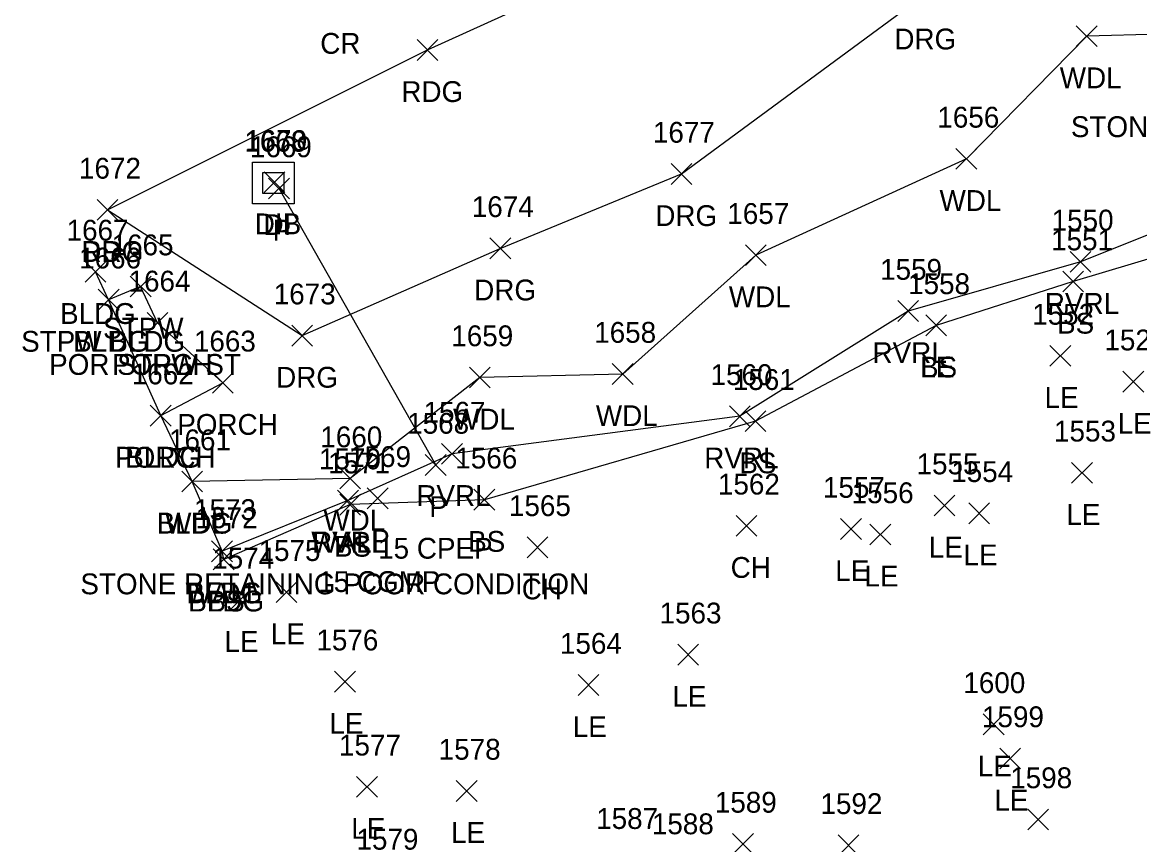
# Model space of a CAD drawing. Extents: x 1620157 to 1620595, y 115111 to 117885.
# Drawn here: x 1620193.5 to 1620300.9, y 115358.6 to 115437.5 of the extents above; entities that cross this region are included whole.
import ezdxf

# ---------------------------------------------------------------- set-up
doc = ezdxf.new("R2010")
doc.units = 0
for name, color, linetype in [('D_A', 7, 'Continuous'), ('D_C', 7, 'Continuous'), ('D_I', 7, 'Continuous'), ('D_TIC', 7, 'Continuous'), ('DCP', 7, 'Continuous'), ('DS', 7, 'Continuous'), ('L_A', 7, 'Continuous'), ('L_C', 7, 'Continuous'), ('L_I', 7, 'Continuous'), ('L_TIC', 7, 'Continuous'), ('LAWA', 7, 'Continuous'), ('LAWE', 7, 'Continuous'), ('LBC', 7, 'Continuous'), ('LBF', 7, 'Continuous'), ('LELB', 7, 'Continuous'), ('LW', 7, 'Continuous'), ('P_A', 7, 'Continuous'), ('P_I', 7, 'Continuous'), ('P_TIC', 7, 'Continuous'), ('PEU', 7, 'Continuous'), ('R_A', 7, 'Continuous'), ('R_I', 7, 'Continuous'), ('R_TIC', 7, 'Continuous'), ('RDG', 7, 'Continuous')]:
    doc.layers.add(name, color=color, linetype=linetype)

msp = doc.modelspace()

# ---------------------------------------------------------------- linework, layer by layer
at = {"layer": 'D_TIC'}
for points in [[(1620216.75, 115421.19), (1620218.75, 115423.19)], [(1620218.75, 115421.19), (1620216.75, 115423.19)], [(1620217.18, 115420.59), (1620219.18, 115422.59)], [(1620219.18, 115420.59), (1620217.18, 115422.59)], [(1620232.23, 115394.04), (1620234.23, 115396.04)], [(1620234.23, 115394.04), (1620232.23, 115396.04)], [(1620226.65, 115390.84), (1620228.65, 115392.84)], [(1620228.65, 115390.84), (1620226.65, 115392.84)]]:
    msp.add_lwpolyline(points, dxfattribs=at)
at = {"layer": 'DCP'}
msp.add_lwpolyline([(1620233.23, 115395.04), (1620218.18, 115421.59)], dxfattribs=at)
at = {"layer": 'DS'}
for p, q in [((1620215.63, 115424.12), (1620219.63, 115424.12)), ((1620215.63, 115420.12), (1620215.63, 115424.12)), ((1620219.63, 115424.12), (1620219.63, 115420.12)), ((1620216.63, 115421.12), (1620216.63, 115423.12)), ((1620216.63, 115423.12), (1620218.63, 115423.12)), ((1620218.63, 115423.12), (1620218.63, 115421.12)), ((1620218.63, 115421.12), (1620216.63, 115421.12)), ((1620217.64, 115422.12), (1620217.64, 115422.12)), ((1620217.64, 115422.12), (1620217.64, 115422.12)), ((1620219.63, 115420.12), (1620215.63, 115420.12))]:
    msp.add_line(p, q, dxfattribs=at)
at = {"layer": 'L_TIC'}
for points in [[(1620294.78, 115435.21), (1620296.78, 115437.21)], [(1620296.78, 115435.21), (1620294.78, 115437.21)], [(1620283.22, 115423.43), (1620285.22, 115425.43)], [(1620285.22, 115423.43), (1620283.22, 115425.43)], [(1620262.99, 115414.18), (1620264.99, 115416.18)], [(1620264.99, 115414.18), (1620262.99, 115416.18)], [(1620294.19, 115413.55), (1620296.19, 115415.55)], [(1620296.19, 115413.55), (1620294.19, 115415.55)], [(1620199.55, 115412.58), (1620201.55, 115414.58)], [(1620201.55, 115412.58), (1620199.55, 115414.58)], [(1620293.48, 115411.65), (1620295.48, 115413.65)], [(1620295.48, 115411.65), (1620293.48, 115413.65)], [(1620203.88, 115411.17), (1620205.88, 115413.17)], [(1620205.88, 115411.17), (1620203.88, 115413.17)], [(1620200.81, 115409.91), (1620202.81, 115411.91)], [(1620202.81, 115409.91), (1620200.81, 115411.91)], [(1620200.81, 115409.91), (1620202.81, 115411.91)], [(1620202.81, 115409.91), (1620200.81, 115411.91)], [(1620277.63, 115408.82), (1620279.63, 115410.82)], [(1620279.63, 115408.82), (1620277.63, 115410.82)], [(1620205.5, 115407.69), (1620207.5, 115409.69)], [(1620207.5, 115407.69), (1620205.5, 115409.69)], [(1620205.5, 115407.69), (1620207.5, 115409.69)], [(1620207.5, 115407.69), (1620205.5, 115409.69)], [(1620280.32, 115407.44), (1620282.32, 115409.44)], [(1620282.32, 115407.44), (1620280.32, 115409.44)], [(1620280.32, 115407.44), (1620282.32, 115409.44)], [(1620282.32, 115407.44), (1620280.32, 115409.44)], [(1620292.24, 115404.51), (1620294.24, 115406.51)], [(1620294.24, 115404.51), (1620292.24, 115406.51)], [(1620236.48, 115402.44), (1620238.48, 115404.44)], [(1620238.48, 115402.44), (1620236.48, 115404.44)], [(1620250.2, 115402.77), (1620252.2, 115404.77)], [(1620252.2, 115402.77), (1620250.2, 115404.77)], [(1620299.26, 115402.04), (1620301.26, 115404.04)], [(1620301.26, 115402.04), (1620299.26, 115404.04)], [(1620211.78, 115401.93), (1620213.78, 115403.93)], [(1620213.78, 115401.93), (1620211.78, 115403.93)], [(1620205.81, 115398.78), (1620207.81, 115400.78)], [(1620207.81, 115398.78), (1620205.81, 115400.78)], [(1620205.81, 115398.78), (1620207.81, 115400.78)], [(1620207.81, 115398.78), (1620205.81, 115400.78)], [(1620261.46, 115398.71), (1620263.46, 115400.71)], [(1620263.46, 115398.71), (1620261.46, 115400.71)], [(1620262.96, 115398.24), (1620264.96, 115400.24)], [(1620264.96, 115398.24), (1620262.96, 115400.24)], [(1620233.8, 115395.1), (1620235.8, 115397.1)], [(1620235.8, 115395.1), (1620233.8, 115397.1)], [(1620208.83, 115392.45), (1620210.83, 115394.45)], [(1620210.83, 115392.45), (1620208.83, 115394.45)], [(1620208.83, 115392.45), (1620210.83, 115394.45)], [(1620210.83, 115392.45), (1620208.83, 115394.45)], [(1620224.02, 115392.74), (1620226.02, 115394.74)], [(1620226.02, 115392.74), (1620224.02, 115394.74)], [(1620294.33, 115393.29), (1620296.33, 115395.29)], [(1620296.33, 115393.29), (1620294.33, 115395.29)], [(1620223.8, 115390.62), (1620225.8, 115392.62)], [(1620225.8, 115390.62), (1620223.8, 115392.62)], [(1620223.8, 115390.62), (1620225.8, 115392.62)], [(1620225.8, 115390.62), (1620223.8, 115392.62)], [(1620224.01, 115390.23), (1620226.01, 115392.23)], [(1620226.01, 115390.23), (1620224.01, 115392.23)], [(1620236.91, 115390.7), (1620238.91, 115392.7)], [(1620238.91, 115390.7), (1620236.91, 115392.7)], [(1620281.12, 115390.14), (1620283.12, 115392.14)], [(1620283.12, 115390.14), (1620281.12, 115392.14)], [(1620284.45, 115389.4), (1620286.45, 115391.4)], [(1620286.45, 115389.4), (1620284.45, 115391.4)], [(1620262.09, 115388.2), (1620264.09, 115390.2)], [(1620264.09, 115388.2), (1620262.09, 115390.2)], [(1620272.13, 115387.89), (1620274.13, 115389.89)], [(1620274.13, 115387.89), (1620272.13, 115389.89)], [(1620274.95, 115387.37), (1620276.95, 115389.37)], [(1620276.95, 115387.37), (1620274.95, 115389.37)], [(1620242.01, 115386.13), (1620244.01, 115388.13)], [(1620244.01, 115386.13), (1620242.01, 115388.13)], [(1620211.7, 115385.75), (1620213.7, 115387.75)], [(1620213.7, 115385.75), (1620211.7, 115387.75)], [(1620211.7, 115385.75), (1620213.7, 115387.75)], [(1620213.7, 115385.75), (1620211.7, 115387.75)], [(1620211.86, 115384.97), (1620213.86, 115386.97)], [(1620213.86, 115384.97), (1620211.86, 115386.97)], [(1620211.86, 115384.97), (1620213.86, 115386.97)], [(1620213.86, 115384.97), (1620211.86, 115386.97)], [(1620217.9, 115381.82), (1620219.9, 115383.82)], [(1620219.9, 115381.82), (1620217.9, 115383.82)], [(1620213.45, 115381.09), (1620215.45, 115383.09)], [(1620215.45, 115381.09), (1620213.45, 115383.09)], [(1620256.48, 115375.82), (1620258.48, 115377.82)], [(1620258.48, 115375.82), (1620256.48, 115377.82)], [(1620223.52, 115373.23), (1620225.52, 115375.23)], [(1620225.52, 115373.23), (1620223.52, 115375.23)], [(1620246.91, 115372.91), (1620248.91, 115374.91)], [(1620248.91, 115372.91), (1620246.91, 115374.91)], [(1620285.84, 115369.13), (1620287.84, 115371.13)], [(1620287.84, 115369.13), (1620285.84, 115371.13)], [(1620287.42, 115365.86), (1620289.42, 115367.86)], [(1620289.42, 115365.86), (1620287.42, 115367.86)], [(1620225.63, 115363.14), (1620227.63, 115365.14)], [(1620227.63, 115363.14), (1620225.63, 115365.14)], [(1620235.21, 115362.74), (1620237.21, 115364.74)], [(1620237.21, 115362.74), (1620235.21, 115364.74)], [(1620290.12, 115360), (1620292.12, 115362)], [(1620292.12, 115360), (1620290.12, 115362)], [(1620261.75, 115357.65), (1620263.75, 115359.65)], [(1620263.75, 115357.65), (1620261.75, 115359.65)], [(1620271.9, 115357.52), (1620273.9, 115359.52)], [(1620273.9, 115357.52), (1620271.9, 115359.52)]]:
    msp.add_lwpolyline(points, dxfattribs=at)
at = {"layer": 'LAWA'}
msp.add_lwpolyline([(1620309.96, 115436.61), (1620295.78, 115436.21), (1620284.22, 115424.43), (1620263.99, 115415.18), (1620251.2, 115403.77), (1620237.48, 115403.44), (1620225.02, 115393.74), (1620209.83, 115393.45)], dxfattribs=at)
at = {"layer": 'LAWE'}
msp.add_lwpolyline([(1620317.3, 115432.59), (1620311.75, 115429.38), (1620305.53, 115418.67), (1620295.19, 115414.55), (1620278.63, 115409.82), (1620262.46, 115399.71), (1620234.8, 115396.1), (1620224.8, 115391.62)], dxfattribs=at)
at = {"layer": 'LBC'}
msp.add_lwpolyline([(1620212.86, 115385.97), (1620212.7, 115386.75), (1620209.83, 115393.45), (1620206.81, 115399.78), (1620201.81, 115410.91), (1620200.55, 115413.58)], dxfattribs=at)
at = {"layer": 'LBF'}
for points in [[(1620206.5, 115408.69), (1620204.88, 115412.17), (1620201.81, 115410.91)], [(1620206.81, 115399.78), (1620212.78, 115402.93), (1620206.5, 115408.69)]]:
    msp.add_lwpolyline(points, dxfattribs=at)
at = {"layer": 'LELB'}
msp.add_lwpolyline([(1620445.93, 115434.7), (1620432.19, 115440.31), (1620415.15, 115443.99), (1620397.76, 115444.06), (1620388.34, 115442.49), (1620368.19, 115442.37), (1620354.52, 115441.05), (1620350.88, 115433.96), (1620346.48, 115432.5), (1620338.97, 115434.36), (1620325.33, 115430.43), (1620316.03, 115427.32), (1620308.72, 115416.91), (1620294.48, 115412.65), (1620281.32, 115408.44), (1620263.96, 115399.24), (1620237.91, 115391.7), (1620225.01, 115391.23), (1620212.86, 115385.97)], dxfattribs=at)
at = {"layer": 'LW'}
msp.add_lwpolyline([(1620224.8, 115391.62), (1620212.7, 115386.75)], dxfattribs=at)
at = {"layer": 'P_TIC'}
for points in [[(1620231.44, 115433.89), (1620233.44, 115435.89)], [(1620233.44, 115433.89), (1620231.44, 115435.89)], [(1620200.7, 115418.53), (1620202.7, 115420.53)], [(1620202.7, 115418.53), (1620200.7, 115420.53)]]:
    msp.add_lwpolyline(points, dxfattribs=at)
at = {"layer": 'PEU'}
msp.add_lwpolyline([(1620201.7, 115419.53), (1620232.44, 115434.89), (1620251.19, 115443.43), (1620278.49, 115455.42), (1620293.82, 115465.58)], dxfattribs=at)
at = {"layer": 'R_TIC'}
for points in [[(1620255.84, 115421.98), (1620257.84, 115423.98)], [(1620257.84, 115421.98), (1620255.84, 115423.98)], [(1620200.7, 115418.53), (1620202.7, 115420.53)], [(1620202.7, 115418.53), (1620200.7, 115420.53)], [(1620238.44, 115414.84), (1620240.44, 115416.84)], [(1620240.44, 115414.84), (1620238.44, 115416.84)], [(1620219.41, 115406.46), (1620221.41, 115408.46)], [(1620221.41, 115406.46), (1620219.41, 115408.46)]]:
    msp.add_lwpolyline(points, dxfattribs=at)
at = {"layer": 'RDG'}
msp.add_lwpolyline([(1620201.7, 115419.53), (1620220.41, 115407.46), (1620239.44, 115415.84), (1620256.84, 115422.98), (1620279.82, 115439.94), (1620293.82, 115465.58)], dxfattribs=at)

# ---------------------------------------------------------------- texts
at = {"layer": 'D_A'}
for s, p in [('DIB', (1620215.85, 115417.19)), ('DI', (1620216.69, 115417.12)), ('P', (1620217.56, 115416.59)), ('P', (1620232.61, 115390.04)), ('P', (1620227.03, 115386.84))]:
    msp.add_text(s, height=2, dxfattribs=at).set_placement(p)
at = {"layer": 'D_C'}
for s, p in [('15 CPEP', (1620227.7, 115386.04)), ('15 CGMP', (1620221.94, 115382.84))]:
    msp.add_text(s, height=2, dxfattribs=at).set_placement(p)
at = {"layer": 'D_I'}
for s, p in [('1668', (1620214.85, 115425.12)), ('1670', (1620214.92, 115425.19)), ('1669', (1620215.38, 115424.59)), ('1568', (1620230.49, 115398.04)), ('1569', (1620224.91, 115394.84))]:
    msp.add_text(s, height=2, dxfattribs=at).set_placement(p)
at = {"layer": 'L_A'}
for s, p in [('WDL', (1620293.19, 115431.21)), ('WDL', (1620281.64, 115419.43)), ('WDL', (1620261.4, 115410.18)), ('RVRL', (1620291.76, 115409.55)), ('BLDG', (1620197.14, 115408.58)), ('BS', (1620292.93, 115407.65)), ('STPW', (1620201.27, 115407.17)), ('STPW BLDG', (1620193.4, 115405.91)), ('BLDG', (1620198.4, 115405.91)), ('RVRL', (1620275.2, 115404.82)), ('POR STPW ST', (1620196.09, 115403.69)), ('PORCH', (1620202.13, 115403.69)), ('BS', (1620279.76, 115403.44)), ('LE', (1620279.8, 115403.44)), ('LE', (1620291.73, 115400.51)), ('WDL', (1620248.62, 115398.77)), ('PORCH', (1620208.4, 115397.93)), ('WDL', (1620234.9, 115398.44)), ('LE', (1620298.75, 115398.04)), ('PORCH', (1620202.43, 115394.78)), ('BLDG', (1620203.4, 115394.78)), ('RVRL', (1620259.03, 115394.71)), ('BS', (1620262.4, 115394.24)), ('RVRL', (1620231.37, 115391.1)), ('LE', (1620293.82, 115389.29)), ('BLDG', (1620206.42, 115388.45)), ('WDL', (1620207.24, 115388.45)), ('WDL', (1620222.44, 115388.74)), ('WALL', (1620221.28, 115386.62)), ('RVRL', (1620221.36, 115386.62)), ('BS', (1620223.46, 115386.23)), ('BS', (1620236.35, 115386.7)), ('LE', (1620280.61, 115386.14)), ('LE', (1620283.94, 115385.4)), ('CH', (1620261.57, 115384.2)), ('LE', (1620271.62, 115383.89)), ('LE', (1620274.43, 115383.37)), ('WALL', (1620209.19, 115381.75)), ('BLDG', (1620209.29, 115381.75)), ('CH', (1620241.5, 115382.13)), ('BLDG', (1620209.45, 115380.97)), ('BS', (1620211.3, 115380.97)), ('LE', (1620217.39, 115377.82)), ('LE', (1620212.94, 115377.09)), ('LE', (1620255.97, 115371.82)), ('LE', (1620223.01, 115369.23)), ('LE', (1620246.4, 115368.91)), ('LE', (1620285.32, 115365.13)), ('LE', (1620286.91, 115361.86)), ('LE', (1620225.12, 115359.14)), ('LE', (1620234.7, 115358.74))]:
    msp.add_text(s, height=2, dxfattribs=at).set_placement(p)
at = {"layer": 'L_C'}
for s, p in [('STONE RETAINING', (1620294.26, 115426.52)), ('STONE RETAINING POOR CONDITION', (1620199.09, 115382.62))]:
    msp.add_text(s, height=2, dxfattribs=at).set_placement(p)
at = {"layer": 'L_I'}
for s, p in [('1656', (1620281.43, 115427.43)), ('1657', (1620261.25, 115418.18)), ('1550', (1620292.41, 115417.55)), ('1667', (1620197.77, 115416.58)), ('1665', (1620202.09, 115415.17)), ('1551', (1620292.36, 115415.65)), ('1666', (1620198.97, 115413.91)), ('1666', (1620198.97, 115413.91)), ('1559', (1620275.93, 115412.82)), ('1664', (1620203.72, 115411.69)), ('1664', (1620203.72, 115411.69)), ('1558', (1620278.62, 115411.44)), ('1558', (1620278.62, 115411.44)), ('1552', (1620290.55, 115408.51)), ('1659', (1620234.73, 115406.44)), ('1658', (1620248.46, 115406.77)), ('1663', (1620210, 115405.93)), ('1520', (1620297.48, 115406.04)), ('1662', (1620204.03, 115402.78)), ('1662', (1620204.03, 115402.78)), ('1560', (1620259.64, 115402.71)), ('1561', (1620261.78, 115402.24)), ('1567', (1620232.06, 115399.1)), ('1660', (1620222.15, 115396.74)), ('1553', (1620292.64, 115397.29)), ('1661', (1620207.61, 115396.45)), ('1661', (1620207.61, 115396.45)), ('1570', (1620222.02, 115394.62)), ('1570', (1620222.02, 115394.62)), ('1566', (1620235.12, 115394.7)), ('1571', (1620222.89, 115394.23)), ('1555', (1620279.43, 115394.14)), ('1554', (1620282.76, 115393.4)), ('1562', (1620260.35, 115392.2)), ('1557', (1620270.44, 115391.89)), ('1556', (1620273.2, 115391.37)), ('1565', (1620240.27, 115390.13)), ('1573', (1620210.01, 115389.75)), ('1573', (1620210.01, 115389.75)), ('1572', (1620210.17, 115388.97)), ('1572', (1620210.17, 115388.97)), ('1574', (1620211.76, 115385.09)), ('1575', (1620216.21, 115385.82)), ('1563', (1620254.74, 115379.82)), ('1576', (1620221.77, 115377.23)), ('1564', (1620245.17, 115376.91)), ('1600', (1620283.93, 115373.13)), ('1599', (1620285.72, 115369.86)), ('1577', (1620223.94, 115367.14)), ('1578', (1620233.52, 115366.74)), ('1598', (1620288.43, 115364)), ('1589', (1620260.05, 115361.65)), ('1592', (1620270.2, 115361.52)), ('1587', (1620248.65, 115360.09)), ('1588', (1620254, 115359.58)), ('1579', (1620225.62, 115358.1))]:
    msp.add_text(s, height=2, dxfattribs=at).set_placement(p)
at = {"layer": 'P_A'}
for s, p in [('CR', (1620222.14, 115434.52)), ('RDG', (1620229.93, 115429.89)), ('RDG', (1620199.19, 115414.53))]:
    msp.add_text(s, height=2, dxfattribs=at).set_placement(p)
at = {"layer": 'P_I'}
msp.add_text('1672', height=2, dxfattribs=at).set_placement((1620198.96, 115422.53))
at = {"layer": 'R_A'}
for p in [(1620277.3, 115434.94), (1620254.33, 115417.98), (1620199.19, 115414.53), (1620236.93, 115410.84), (1620217.9, 115402.46)]:
    msp.add_text('DRG', height=2, dxfattribs=at).set_placement(p)
at = {"layer": 'R_I'}
for s, p in [('1677', (1620254.1, 115425.98)), ('1672', (1620198.96, 115422.53)), ('1674', (1620236.7, 115418.84)), ('1673', (1620217.67, 115410.46))]:
    msp.add_text(s, height=2, dxfattribs=at).set_placement(p)

doc.saveas('drawing.dxf')
